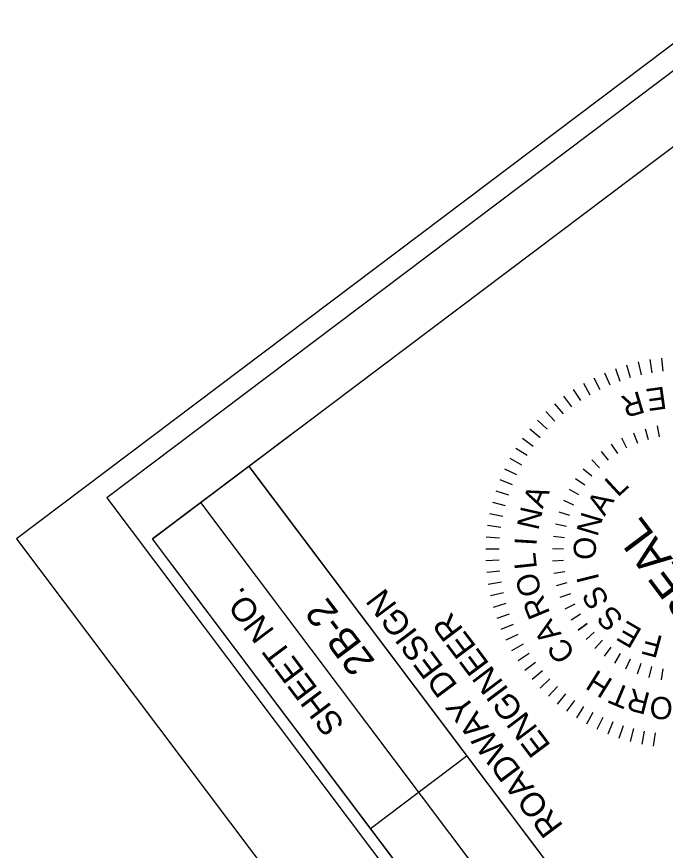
# Model space of a CAD drawing. Extents: x 1263113 to 1265001, y 775064 to 777068.
# Drawn here: x 1263113.4 to 1263247.8, y 776344.6 to 776517.2 of the extents above; entities that cross this region are included whole.
import ezdxf

# ---------------------------------------------------------------- set-up
doc = ezdxf.new("R2010")
doc.units = 0
for name, color, linetype in [('Default', 7, 'Continuous'), ('Sheet Data Field CELL', 7, 'Continuous'), ('Sheet Plan CELL', 7, 'Continuous'), ('Sheet Plot Border Inside CELL', 7, 'Continuous'), ('Sheet Plot Border Outside CELL', 7, 'Continuous'), ('Sheet Typical CELL', 7, 'Continuous')]:
    doc.layers.add(name, color=color, linetype=linetype)

msp = doc.modelspace()

# ---------------------------------------------------------------- linework, layer by layer
at = {"layer": 'Default'}
for p, q in [((1263244.56, 776446.21), (1263245, 776443.49)), ((1263246.98, 776446.53), (1263247.26, 776443.79)), ((1263237.46, 776444.39), (1263238.39, 776441.78)), ((1263239.79, 776445.14), (1263240.55, 776442.48)), ((1263242.16, 776445.74), (1263242.77, 776443.05)), ((1263235.18, 776443.49), (1263236.27, 776440.96)), ((1263230.81, 776441.31), (1263232.19, 776438.92)), ((1263232.96, 776442.47), (1263234.2, 776440)), ((1263228.73, 776440.02), (1263230.25, 776437.72)), ((1263226.73, 776438.61), (1263228.39, 776436.41)), ((1263224.82, 776437.08), (1263226.61, 776434.98)), ((1263223.01, 776435.44), (1263224.92, 776433.45)), ((1263221.3, 776433.7), (1263223.32, 776431.83)), ((1263246.14, 776432.47), (1263246.56, 776430.21)), ((1263219.69, 776431.85), (1263221.83, 776430.1)), ((1263241.19, 776431.04), (1263242.04, 776428.91)), ((1263243.63, 776431.88), (1263244.27, 776429.67)), ((1263218.2, 776429.91), (1263220.44, 776428.29)), ((1263239.83, 776427.89), (1263238.77, 776429.93)), ((1263216.83, 776427.88), (1263219.17, 776426.41)), ((1263234.51, 776427.19), (1263235.94, 776425.38)), ((1263236.61, 776428.68), (1263237.86, 776426.75)), ((1263215.6, 776425.77), (1263218.01, 776424.44)), ((1263232.57, 776425.49), (1263234.16, 776423.83)), ((1263214.48, 776423.6), (1263216.97, 776422.42)), ((1263230.8, 776423.62), (1263232.55, 776422.12)), ((1263213.5, 776421.36), (1263216.06, 776420.33)), ((1263229.22, 776421.58), (1263231.1, 776420.25)), ((1263212.65, 776419.06), (1263215.27, 776418.19)), ((1263227.84, 776419.4), (1263229.84, 776418.27)), ((1263211.95, 776416.72), (1263214.61, 776416.01)), ((1263226.68, 776417.09), (1263228.78, 776416.16)), ((1263211.39, 776414.34), (1263214.09, 776413.79)), ((1263225.74, 776414.69), (1263227.93, 776413.97)), ((1263210.97, 776411.93), (1263213.7, 776411.54)), ((1263225.05, 776412.21), (1263227.29, 776411.7)), ((1263210.7, 776409.5), (1263213.45, 776409.28)), ((1263224.6, 776409.67), (1263226.88, 776409.38)), ((1263210.58, 776407.05), (1263213.34, 776407)), ((1263224.39, 776407.1), (1263226.69, 776407.03)), ((1263210.61, 776404.61), (1263213.36, 776404.72)), ((1263224.43, 776404.52), (1263226.73, 776404.68)), ((1263210.78, 776402.17), (1263213.52, 776402.45)), ((1263224.72, 776401.96), (1263226.99, 776402.33)), ((1263211.1, 776399.74), (1263213.82, 776400.19)), ((1263225.26, 776399.44), (1263227.48, 776400.03)), ((1263211.57, 776397.34), (1263214.25, 776397.95)), ((1263226.04, 776396.98), (1263228.19, 776397.78)), ((1263212.17, 776394.97), (1263214.83, 776395.74)), ((1263227.05, 776394.61), (1263229.12, 776395.61)), ((1263212.92, 776392.65), (1263215.52, 776393.58)), ((1263228.28, 776392.35), (1263230.24, 776393.55)), ((1263213.81, 776390.37), (1263216.35, 776391.45)), ((1263229.73, 776390.21), (1263231.57, 776391.59)), ((1263231.57, 776391.59), (1263229.73, 776390.21)), ((1263214.84, 776388.15), (1263217.31, 776389.38)), ((1263231.38, 776388.23), (1263233.07, 776389.78)), ((1263216, 776386), (1263218.39, 776387.38)), ((1263233.21, 776386.41), (1263234.75, 776388.12)), ((1263235.2, 776384.78), (1263236.57, 776386.63)), ((1263217.29, 776383.92), (1263219.59, 776385.44)), ((1263237.35, 776383.35), (1263238.53, 776385.33)), ((1263239.63, 776382.14), (1263240.61, 776384.21)), ((1263218.7, 776381.92), (1263220.9, 776383.58)), ((1263242.01, 776381.14), (1263242.79, 776383.31)), ((1263244.47, 776380.39), (1263245.04, 776382.62)), ((1263247, 776379.88), (1263247.35, 776382.15)), ((1263220.23, 776380.01), (1263222.33, 776381.8)), ((1263221.87, 776378.2), (1263223.86, 776380.1)), ((1263223.61, 776376.48), (1263225.48, 776378.51)), ((1263225.46, 776374.88), (1263227.21, 776377.02)), ((1263227.4, 776373.39), (1263229.02, 776375.63)), ((1263229.43, 776372.02), (1263230.9, 776374.36)), ((1263231.53, 776370.78), (1263232.87, 776373.2)), ((1263233.71, 776369.66), (1263234.89, 776372.16)), ((1263235.95, 776368.68), (1263236.98, 776371.25)), ((1263238.25, 776367.84), (1263239.12, 776370.46)), ((1263240.59, 776367.14), (1263241.3, 776369.8)), ((1263242.97, 776366.58), (1263243.52, 776369.28)), ((1263245.38, 776366.16), (1263245.77, 776368.89))]:
    msp.add_line(p, q, dxfattribs=at)
at = {"layer": 'Sheet Plan CELL'}
msp.add_lwpolyline([(1263251.41, 776491.76), (1263330.45, 776386.82), (1263240.62, 776319.15), (1263161.57, 776424.1)], dxfattribs=at)
at = {"layer": 'Sheet Plot Border Inside CELL'}
msp.add_lwpolyline([(1264977.07, 775721.54), (1263974.73, 777052.27), (1263132.03, 776417.56), (1264134.37, 775086.81)], close=True, dxfattribs=at)
at = {"layer": 'Sheet Plot Border Outside CELL'}
msp.add_lwpolyline([(1263113.35, 776409.12), (1264126.21, 775064.39), (1265000.86, 775723.19), (1263988, 777067.91)], close=True, dxfattribs=at)
at = {"layer": 'Sheet Typical CELL'}
for p, q in [((1263141.54, 776409.07), (1263980.25, 777040.79)), ((1263171.55, 776431.67), (1263141.54, 776409.07)), ((1263281.92, 776264.37), (1263161.57, 776424.15)), ((1263271.91, 776256.83), (1263151.56, 776416.61)), ((1263261.89, 776249.28), (1263141.54, 776409.07)), ((1264044, 775210.92), (1263141.54, 776409.07)), ((1263186.69, 776349.13), (1263206.71, 776364.22))]:
    msp.add_line(p, q, dxfattribs=at)

# ---------------------------------------------------------------- texts
at = {"layer": 'Default'}
for s, height, rotation, p in [('R', 4.6, 196.6068, (1263242.54, 776439.75)), ('E', 4.6, 187.9341, (1263247.67, 776440.65)), ('L', 4.6, 42.805, (1263237.94, 776417.58)), ('A', 4.6, 67.4515, (1263222.35, 776415.17)), ('A', 4.6, 58.1013, (1263235.19, 776413.65)), ('N', 4.6, 77.219, (1263221.46, 776410.71)), ('N', 4.6, 73.3975, (1263233.7, 776409.38)), ('SEAL', 6.899, 126.9344, (1263256.83, 776395.12)), ('I', 4.6, 86.5135, (1263221.11, 776407.57)), ('O', 4.6, 88.6938, (1263233.37, 776404.7)), ('L', 4.6, 96.089, (1263221.21, 776403)), ('O', 4.6, 109.2252, (1263222.38, 776398.03)), ('I', 4.6, 103.99, (1263234.16, 776400.66)), ('S', 4.6, 119.2863, (1263236.31, 776396.16)), ('R', 4.6, 112.2821, (1263224, 776393.68)), ('S', 4.6, 134.5825, (1263239.37, 776392.72)), ('A', 4.6, 124.2914, (1263226.38, 776389.38)), ('E', 4.6, 149.8788, (1263243.23, 776390.22)), ('F', 4.6, 165.175, (1263247.51, 776388.84)), ('C', 4.6, 124.2914, (1263229.33, 776385.31)), ('H', 4.6, 148.0021, (1263237.19, 776379.78)), ('T', 4.6, 157.434, (1263241.01, 776378.02)), ('R', 4.6, 165.595, (1263244.92, 776377.09)), ('O', 4.6, 178.6517, (1263249.4, 776376.29))]:
    msp.add_text(s, height=height, rotation=rotation, dxfattribs=at).set_placement(p)
at = {"layer": 'Sheet Data Field CELL'}
msp.add_text('2B-2', height=6, rotation=126.9874, dxfattribs=at).set_placement((1263187.8, 776383.73))
at = {"layer": 'Sheet Plan CELL'}
for s, height, p in [('SHEET NO.', 5, (1263181.49, 776370.7)), ('ROADWAY DESIGN', 4.9986, (1263226.79, 776349.64)), ('ENGINEER', 4.999, (1263224.21, 776366.28))]:
    msp.add_text(s, height=height, rotation=126.9874, dxfattribs=at).set_placement(p)

doc.saveas('drawing.dxf')
